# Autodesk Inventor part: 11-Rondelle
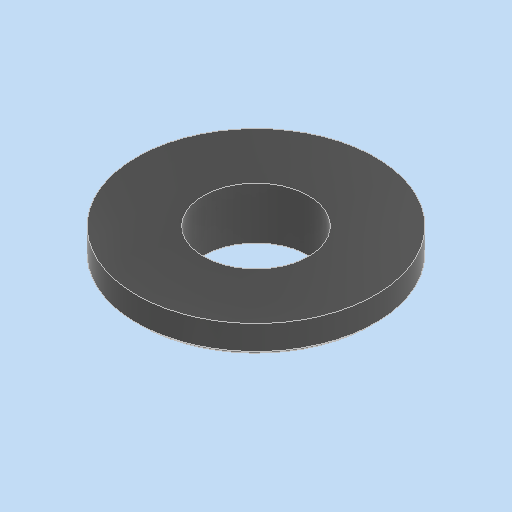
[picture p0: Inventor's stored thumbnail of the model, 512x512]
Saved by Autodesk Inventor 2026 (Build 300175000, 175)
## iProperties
Created: 2025-12
Part Number: 11-Rondelle
Material: Générique
Document SubType Name: Modeling
Designer: thierry.jost
Density: 1 g/cm^3
Appearance: Gris foncé
Author: thierry.jost
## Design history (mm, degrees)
sketch "Esquisse1"
  geometry: L1 (0, 5.5)-(0, 12.5); L2 (0, 12.5)-(-3.035, 12.5); L3 (-3.035, 12.5)-(-3.035, 7); L4 (-3.035, 7)-(-5.431, 7); L5 (-5.431, 7)-(-5.431, 5.5); L6 (-5.431, 5.5)-(0, 5.5); L7 (0, 0)-(-16.454, 0)
  constraints: 14 end point, 5 perpendicular, 1 horizontal, 1 vertical
  dimensions: "d0" = 25 diameter of L2 L7; "d1" = 14 diameter of L4 L7; "d2" = 11 diameter of L6 L7
revolve "Révolution1" sketch "Esquisse1" stored, may be unused: angle "d3" = 90 deg
chamfer "Chanfrein1" distance "d4" = 0.5; stored, may be unused: second distance "d5" = 2, angle "d6" = 45 deg
node "Solide1"
